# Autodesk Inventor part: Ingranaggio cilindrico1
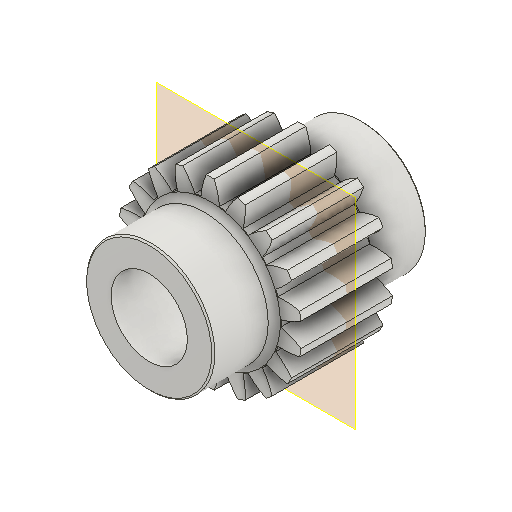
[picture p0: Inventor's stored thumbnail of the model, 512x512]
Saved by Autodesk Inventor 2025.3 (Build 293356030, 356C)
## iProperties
CustomPartVersion: 1
Created: 2026-05
Part Number: Ingranaggio cilindrico1
Material: Acciaio inossidabile
Document SubType Name: Modeling
Designer: R5800u
Categories: <?xml version="1.0" encoding="UTF-16"?> <MemberInstance><Categories><FamilyTemplate><FamilyTemplateParameter ValueType="xs:double" Id="1" ObjectReferenceKey="da
Density: 8 g/cm^3
Appearance: Acciaio
Author: R5800u
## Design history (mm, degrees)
sketch "Sketch1"
  geometry: C1 r 30 at (0, 0)
  constraints: 1 centre point
  dimensions: "d0" = 60 diameter of C1 (= da_da)
extrude "Extrusion1" new body sketch "Sketch1" distance "d1" = 30 (= da_b); taper "d2" = 0 deg
workplane "Work Plane2"
feature "Diametro primitivo" dims "d4" = 10, "d5" = 0
workplane "Work Plane8"
workplane "Work Plane9"
feature "Ingranaggio cilindrico" dims "da_b" = 30, "da_d" = 54, "da_aw" = 162, "da_da" = 60, "da_df" = 46.5, "da_dw" = 54, angle "da_beta" = 0 deg, "da_lefttooth" = 0, "da_righttooth" = 0
sketch "Schizzo3"
  geometry: A1 r 23.25 centre (0, 0) between (-18.445, -14.154) and (-17.142, -15.707) reference; 2 further points
  constraints: 1 coincident
hole "Foro1" sketch "Schizzo3" at (0, 0) diameter "d49" = 25; stored, may be unused: countersink angle "d53" = 90 deg, drill point angle "d55" = 118 deg; dims "d50" = 6, "d51" = 4, "d52" = 2, "d54" = 8
sketch "Schizzo4"
  geometry: C1 r 12.5 at (0, 0) reference; C2 r 21 at (0, 0); 1 further point
  constraints: 1 centre point, 1 coincident
  dimensions: "d56" = 42 diameter of C2
extrude "Estrusione2" join sketch "Schizzo4" distance "d57" = 20; taper "d58" = 0 deg
node "Piano di lavoro11"
fillet "Raccordo2" dims "d60" = 2
mirror "Speculare1"
chamfer "Smusso1" distance "d61" = 0.5; stored, may be unused: second distance "d62" = 2, angle "d63" = 45 deg
body "Solid1"
sketch "Sketch2"
  geometry: C1 r 30 at (0, 0) reference; C2 r 27 at (0, 0)
  constraints: 1 centre point, 1 coincident
  dimensions: "d3" = 54 diameter of C2 (= da_d)
body "Srf1"
other parameters: "d16" = 162 (= da_aw), "d17" = 0, "d34" = 10 deg (computed from da_z), "d39" = 0, "d41" = 0, "d43" = 162 (= da_aw), "d46" = 162 (= da_aw), "d47" = 0, "d48" = 0
